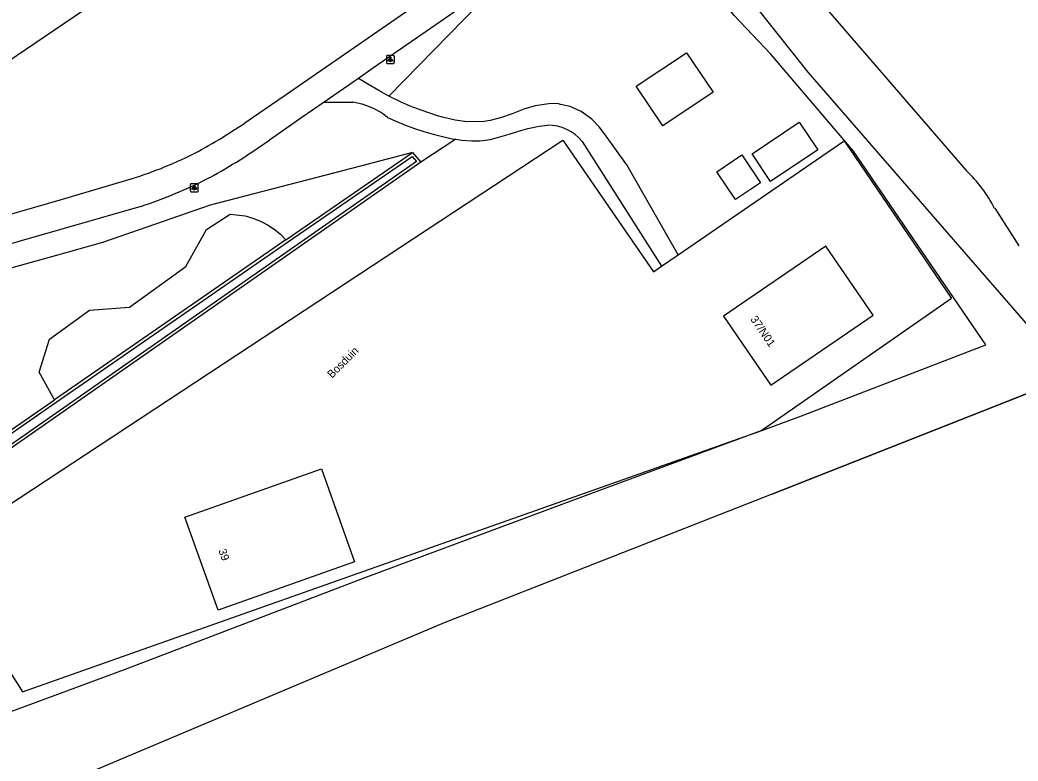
# Model space of a CAD drawing. Extents: x 156664 to 157568, y 383571 to 384421.
# Drawn here: x 157232.2 to 157356.9, y 383716.6 to 383809.2 of the extents above; entities that cross this region are included whole.
import ezdxf

# ---------------------------------------------------------------- set-up
doc = ezdxf.new("R2010")
doc.units = 0
for name, color, linetype in [('IMGEO_Fietspad_gesloten', 7, 'Continuous'), ('IMGEO_Gemengd_bos', 7, 'Continuous'), ('IMGEO_Groenvoorziening', 7, 'Continuous'), ('IMGEO_Hek', 7, 'Continuous'), ('IMGEO_Lichtpunt', 7, 'Continuous'), ('IMGEO_Openbare_ruimte_label', 7, 'Continuous'), ('IMGEO_Pand', 7, 'Continuous'), ('IMGEO_Pand_nummerreeks', 7, 'Continuous'), ('IMGEO_Rijbaan_lokaal_halfverhard', 7, 'Continuous'), ('IMGEO_Waterloop', 7, 'Continuous')]:
    doc.layers.add(name, color=color, linetype=linetype)

msp = doc.modelspace()

# ---------------------------------------------------------------- linework, layer by layer
at = {"layer": 'IMGEO_Fietspad_gesloten'}
for points in [[(157261.23, 383796.98), (157265.18, 383799.68), (157287.92, 383815.45)], [(157291.81, 383813.9), (157276.35, 383803.18), (157274.46, 383801.87)], [(157270.16, 383798.88), (157267.26, 383796.88), (157263.34, 383794.17)], [(157195.53, 383774.66), (157210.71, 383779.06), (157226.49, 383783.6), (157237.48, 383786.76), (157246.06, 383789.32)], [(157247.26, 383785.88), (157226.91, 383780.04), (157198.98, 383771.99)]]:
    msp.add_lwpolyline(points, dxfattribs=at)
for centre, radius, start, end in [((157221.57, 383853.22), 68.82, 298.521, 305.1909), ((157222.47, 383851.26), 70.22, 298.4029, 305.5969), ((157231.49, 383836.75), 49.62, 287.073, 297.5427), ((157229.56, 383840.05), 56.99, 288.09, 297.4886)]:
    msp.add_arc(centre, radius, start, end, dxfattribs=at)
at = {"layer": 'IMGEO_Gemengd_bos'}
for points in [[(157316.21, 383828.93), (157323.18, 383821.92), (157350.4, 383790.37)], [(157373.35, 383759), (157362.95, 383765.45), (157357.05, 383772.24), (157330.66, 383802.65), (157323.39, 383811.81), (157318.54, 383817.64), (157311.61, 383824.37)], [(157324.87, 383757.87), (157329.6, 383759.61), (157352.85, 383768.57), (157336.33, 383792.76), (157325.98, 383804.89), (157321.42, 383809.74), (157317.52, 383814.7), (157310.51, 383823.61)], [(157353.97, 383785.64), (157356.97, 383780.95)], [(157412.12, 383680.62), (157406.86, 383688.86), (157405.2, 383690.91), (157403.34, 383692.77), (157393.32, 383702.26), (157391.63, 383719.71), (157368.14, 383749.98), (157358.35, 383762.61), (157326.23, 383749.98), (157285.19, 383733.84), (157232.49, 383711.6), (157231.84, 383711.33)], [(157324.87, 383757.87), (157303.45, 383749.98), (157275.26, 383739.46), (157245.19, 383727.96), (157225.78, 383720.82)]]:
    msp.add_lwpolyline(points, dxfattribs=at)
msp.add_arc((157337.61, 383777.04), 18.47, 27.7167, 46.1817, dxfattribs=at)
at = {"layer": 'IMGEO_Groenvoorziening'}
for points in [[(157291.73, 383845.37), (157191.18, 383777.22)], [(157289.54, 383811.19), (157278.27, 383799.66)], [(157315.47, 383805.08), (157318.77, 383800.15), (157312.48, 383795.95), (157309.18, 383800.88), (157315.47, 383805.08)], [(157323.67, 383792.45), (157329.55, 383796.38), (157331.86, 383792.93), (157325.97, 383789), (157323.67, 383792.45)], [(157221.79, 383742.66), (157300, 383794.17), (157311.32, 383777.7), (157312.33, 383778.4)], [(157286.63, 383794.26), (157282.25, 383791.41)], [(157314.43, 383779.84), (157335.15, 383794.07), (157348.57, 383774.35), (157324.87, 383757.87)], [(157281.22, 383792.61), (157274.71, 383790.91), (157255.94, 383786.01), (157248.02, 383783.28), (157242.47, 383781.37), (157236.56, 383779.71), (157225.73, 383776.69), (157213.74, 383773.59), (157209.58, 383771.59), (157205.96, 383767), (157209.46, 383759.99), (157211.8, 383751.79)], [(157265.4, 383781.69), (157281.22, 383792.61)], [(157281.22, 383792.61), (157282.25, 383791.41)], [(157322.38, 383792.31), (157324.71, 383788.83), (157321.56, 383786.72), (157319.23, 383790.2), (157322.38, 383792.31)], [(157282.25, 383791.41), (157222.91, 383750), (157213.39, 383743.35)], [(157236.47, 383761.7), (157234.57, 383765.16), (157235.85, 383769.3), (157240.86, 383772.93), (157245.84, 383773.29), (157252.89, 383778.38), (157255.49, 383783.01), (157258.45, 383784.9), (157260.32, 383784.68), (157261.28, 383784.41), (157262.21, 383784.05), (157263.1, 383783.59), (157263.93, 383783.04), (157264.7, 383782.4), (157265.4, 383781.69)], [(157265.4, 383781.69), (157236.47, 383761.7)], [(157225.31, 383753.99), (157236.47, 383761.7)], [(157229.3, 383730.17), (157232.47, 383725.23), (157324.87, 383757.87)]]:
    msp.add_lwpolyline(points, dxfattribs=at)
at = {"layer": 'IMGEO_Hek'}
for points in [[(157326.23, 383749.98), (157358.35, 383762.61), (157368.14, 383749.98)], [(157326.23, 383749.98), (157285.19, 383733.84), (157232.49, 383711.6)]]:
    msp.add_lwpolyline(points, dxfattribs=at)
at = {"layer": 'IMGEO_Lichtpunt'}
for p, q in [((157277.95, 383804.64), (157277.95, 383803.84)), ((157277.95, 383804.64), (157277.95, 383803.84)), ((157278.85, 383804.74), (157278.05, 383804.74)), ((157278.85, 383804.74), (157278.05, 383804.74)), ((157278.95, 383803.84), (157278.95, 383804.64)), ((157278.95, 383803.84), (157278.95, 383804.64)), ((157278.05, 383803.74), (157278.85, 383803.74)), ((157278.05, 383803.74), (157278.85, 383803.74)), ((157253.45, 383788.61), (157253.45, 383787.8)), ((157253.45, 383788.61), (157253.45, 383787.8)), ((157254.36, 383788.7), (157253.55, 383788.7)), ((157254.36, 383788.7), (157253.55, 383788.7)), ((157254.45, 383787.8), (157254.45, 383788.61)), ((157254.45, 383787.8), (157254.45, 383788.61)), ((157253.55, 383787.71), (157254.36, 383787.71)), ((157253.55, 383787.71), (157254.36, 383787.71))]:
    msp.add_line(p, q, dxfattribs=at)
for points in [[(157278.33, 383804.31), (157278.36, 383804.28), (157278.18, 383804.02), (157278.14, 383804.05), (157278.33, 383804.31)], [(157278.43, 383804.26), (157278.47, 383804.26), (157278.47, 383803.94), (157278.43, 383803.94), (157278.43, 383804.26)], [(157278.54, 383804.28), (157278.58, 383804.31), (157278.76, 383804.04), (157278.72, 383804.02), (157278.54, 383804.28)], [(157253.83, 383788.27), (157253.87, 383788.24), (157253.68, 383787.98), (157253.64, 383788.01), (157253.83, 383788.27)], [(157253.93, 383788.22), (157253.98, 383788.22), (157253.98, 383787.9), (157253.93, 383787.9), (157253.93, 383788.22)], [(157254.04, 383788.24), (157254.08, 383788.27), (157254.26, 383788.01), (157254.23, 383787.98), (157254.04, 383788.24)]]:
    msp.add_lwpolyline(points, dxfattribs=at)
for centre in [(157278.45, 383804.44), (157253.95, 383788.41)]:
    msp.add_circle(centre, 0.0994, dxfattribs=at)
for centre, start, end in [((157278.05, 383804.64), 90, 180), ((157278.05, 383804.64), 90, 180), ((157278.85, 383804.64), 0, 90), ((157278.85, 383804.64), 0, 90), ((157278.05, 383803.84), 180, 270), ((157278.05, 383803.84), 180, 270), ((157278.85, 383803.84), 270, 0), ((157278.85, 383803.84), 270, 360), ((157253.55, 383788.61), 90, 180), ((157253.55, 383788.61), 90, 180), ((157254.36, 383788.61), 0, 90), ((157254.36, 383788.61), 0, 90), ((157253.55, 383787.8), 180, 270), ((157253.55, 383787.8), 180, 270), ((157254.36, 383787.8), 270, 0), ((157254.36, 383787.8), 270, 360)]:
    msp.add_arc(centre, 0.0946, start, end, dxfattribs=at)
at = {"layer": 'IMGEO_Pand'}
for points in [[(157325.99, 383763.52), (157338.79, 383772.29), (157332.88, 383780.92), (157320.07, 383772.16), (157325.99, 383763.52)], [(157269.85, 383753.1), (157273.98, 383741.47), (157256.92, 383735.42), (157252.78, 383747.06), (157269.85, 383753.1)]]:
    msp.add_lwpolyline(points, dxfattribs=at)
at = {"layer": 'IMGEO_Rijbaan_lokaal_halfverhard'}
for points in [[(157274.46, 383801.87), (157270.16, 383798.88)], [(157278.27, 383799.66), (157276.99, 383800.37), (157275.72, 383801.11), (157274.46, 383801.87)], [(157314.43, 383779.84), (157307.98, 383791.06), (157307.14, 383792.27), (157306.29, 383793.46), (157305.21, 383794.94), (157304.53, 383795.81), (157303.64, 383796.76), (157302.29, 383797.73), (157300.9, 383798.34), (157299.7, 383798.62), (157299.44, 383798.68), (157298.54, 383798.74), (157296.54, 383798.46), (157295.13, 383798.02), (157293.65, 383797.46), (157292.33, 383796.99), (157290.92, 383796.6), (157290.16, 383796.47), (157288.02, 383796.45), (157286.56, 383796.66), (157284.98, 383797.03), (157284.34, 383797.21), (157282.28, 383797.88), (157280.91, 383798.41), (157279.7, 383798.95), (157278.27, 383799.66)], [(157270.16, 383798.88), (157273.75, 383798.9)], [(157278.1, 383796.98), (157279.34, 383796.45), (157280.33, 383796.04), (157281.47, 383795.62), (157282.62, 383795.24), (157283.79, 383794.9), (157284.98, 383794.59), (157286.17, 383794.33), (157286.63, 383794.26)], [(157286.63, 383794.26), (157287.38, 383794.14), (157288.59, 383794.05), (157289.62, 383794.08), (157290.98, 383794.25), (157292.13, 383794.57), (157293.29, 383794.91), (157294.46, 383795.28), (157295.64, 383795.62), (157297.04, 383795.92), (157298.08, 383796.03)], [(157302.43, 383793.97), (157312.33, 383778.4)], [(157312.33, 383778.4), (157314.43, 383779.84)]]:
    msp.add_lwpolyline(points, dxfattribs=at)
for centre, radius, start, end in [((157272.32, 383789.78), 9.24, 51.2288, 81.0445), ((157298.08, 383790.41), 5.62, 39.2949, 90.0557)]:
    msp.add_arc(centre, radius, start, end, dxfattribs=at)
at = {"layer": 'IMGEO_Waterloop'}
msp.add_lwpolyline([(157281.71, 383791.48), (157222.7, 383750.3), (157213.49, 383743.87), (157212.85, 383744.92), (157219.75, 383749.7), (157225.52, 383753.69), (157236.68, 383761.4), (157265.61, 383781.39), (157281.16, 383792.13), (157281.71, 383791.48)], dxfattribs=at)

# ---------------------------------------------------------------- texts
at = {"layer": 'IMGEO_Openbare_ruimte_label'}
msp.add_text('Bosduin', height=1, rotation=45, dxfattribs=at).set_placement((157271.15, 383764.33))
at = {"layer": 'IMGEO_Pand_nummerreeks'}
for s, rotation, p in [('37/N01', 304.3679, (157323.39, 383771.78)), ('39', 289.29, (157256.95, 383742.9))]:
    msp.add_text(s, height=1, rotation=rotation, dxfattribs=at).set_placement(p)

doc.saveas('drawing.dxf')
